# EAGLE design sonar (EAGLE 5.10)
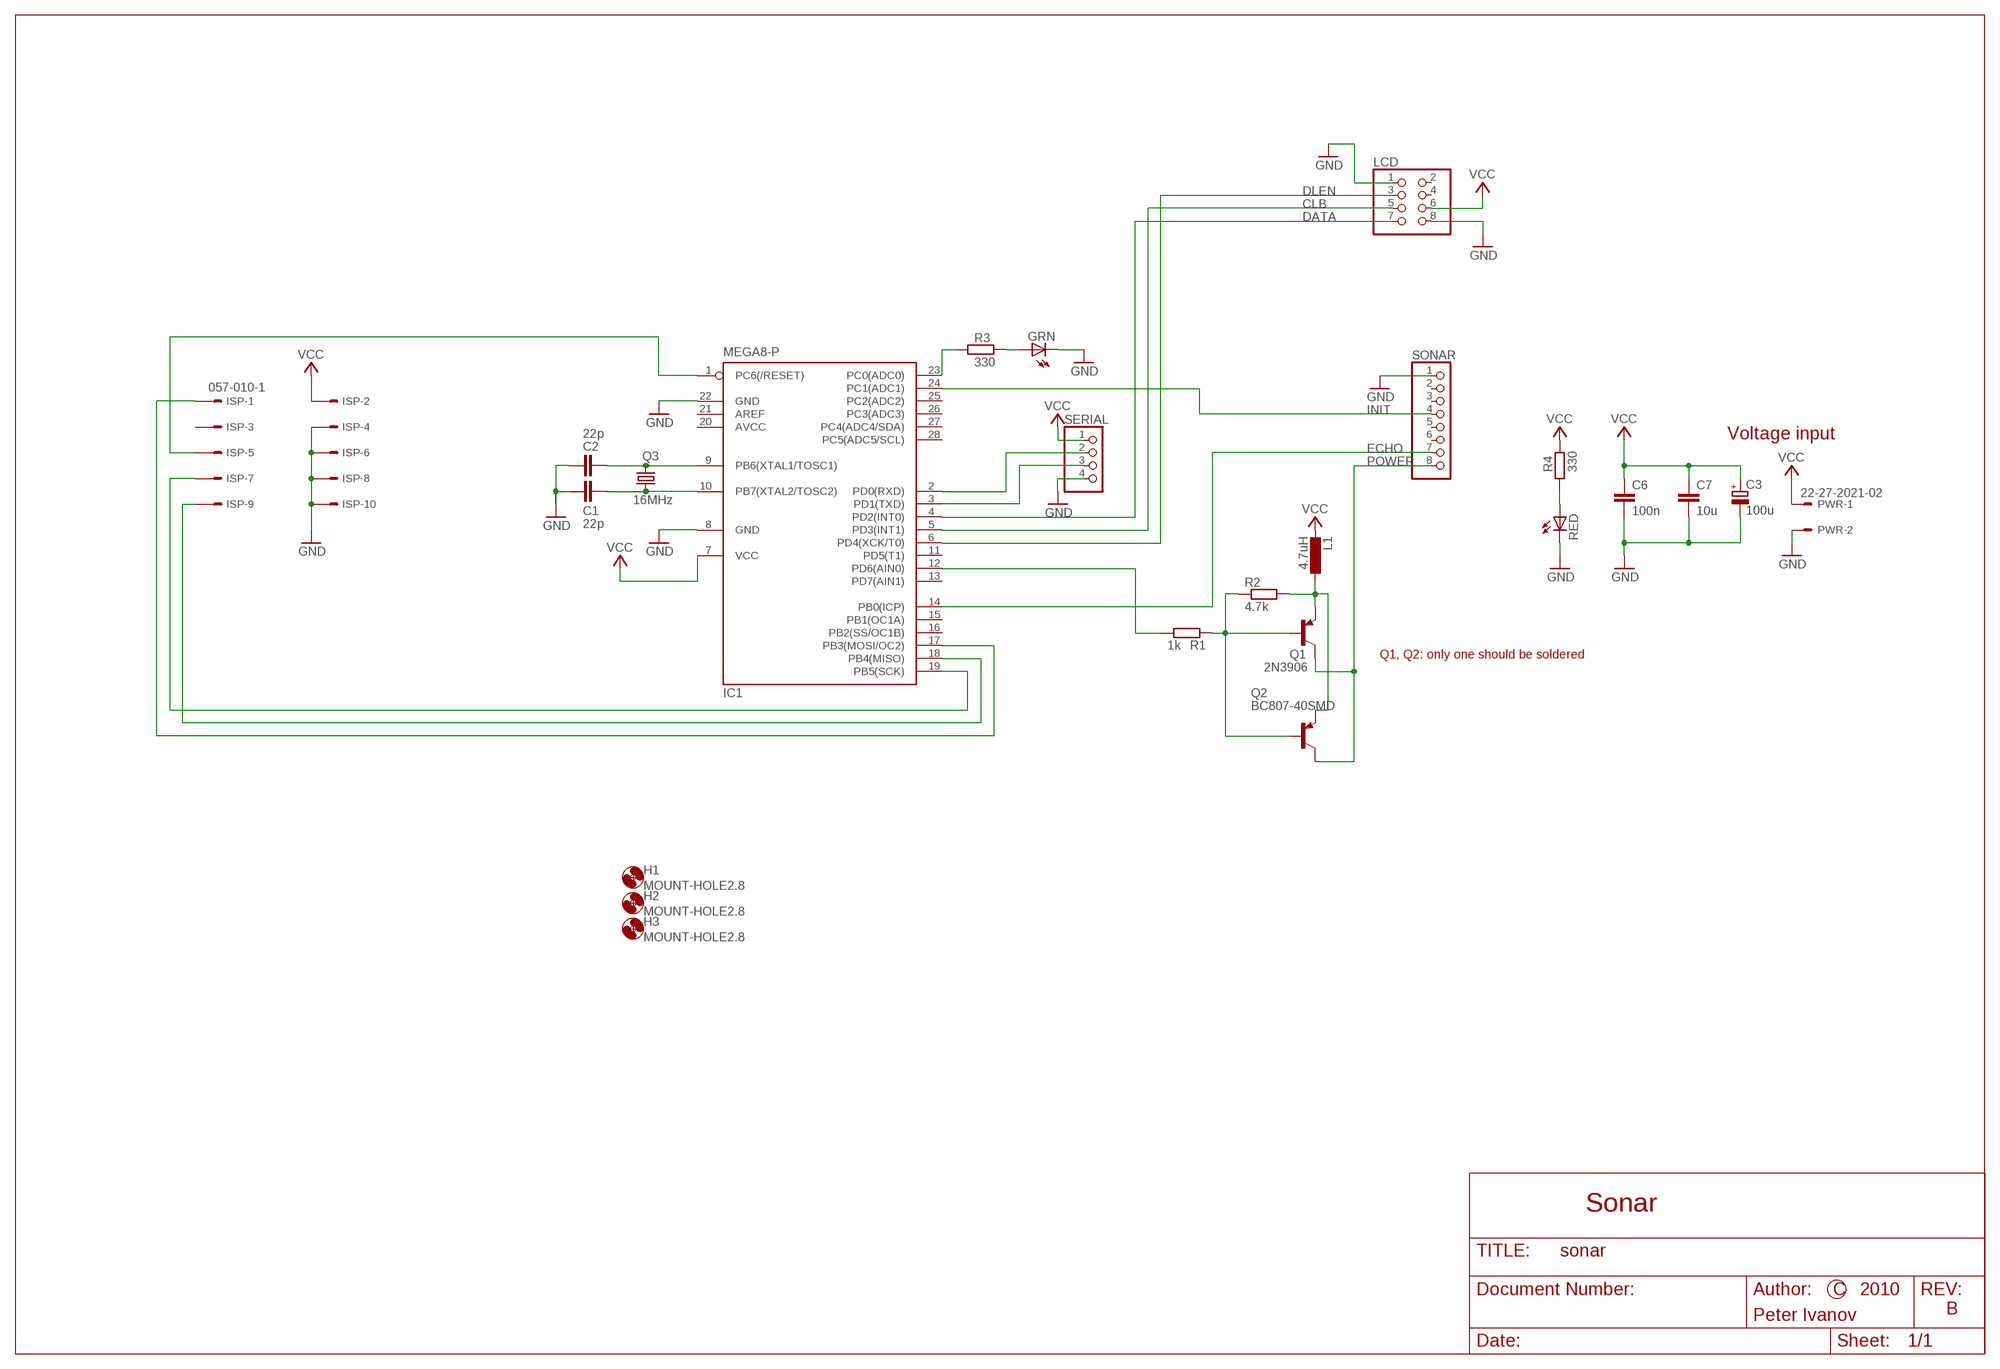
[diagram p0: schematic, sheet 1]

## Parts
C1  22p  C-EUC0805  [C0805]
C2  22p  C-EUC0805  [C0805]
C3  100u  CPOL-EUE2-5  [E2-5]
C6  100n  C-EUC0805  [C0805]
C7  10u  C-EUC1210  [C1210]
GRN  LED3MM  [LED3MM]
H1  MOUNT-HOLE2.8  [2,8]
H2  MOUNT-HOLE2.8  [2,8]
H3  MOUNT-HOLE2.8  [2,8]
IC1  MEGA8-P  [DIL28-3]
ISP  057-010-1  [057-010-1]
L1  4.7uH  L-EUL3230M  [L3230M]
LCD  PINHD-2X4  [2X04]
PWR  22-27-2021-02  [6410-02]
Q1  2N3906  [TO92]
Q2  BC807-40SMD  [SOT23-BEC]
Q3  16MHz  CRYSTALHC49S  [HC49/S]
R1  1k  R-EU_R0805  [R0805]
R2  4.7k  R-EU_R0805  [R0805]
R3  330  R-EU_R0805  [R0805]
R4  330  R-EU_R0805  [R0805]
RED  LED3MM  [LED3MM]
SERIAL  PINHD-1X4  [1X04]
SONAR  PINHD-1X8  [1X08]

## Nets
CLB: IC1.5(PD3(INT1)) LCD.5
DATA: IC1.4(PD2(INT0)) LCD.7
DLEN: IC1.6(PD4(XCK/T0)) LCD.3
ECHO: IC1.14(PB0(ICP)) SONAR.7
GND: C1.1 C2.1 C3.- C6.2 C7.2 GRN.K(C) IC1.8(GND) IC1.22(GND) ISP.4 ISP.6 ISP.8 ISP.10 LCD.1 LCD.8 PWR.2 RED.K(C) SERIAL.4 SONAR.1
INIT: IC1.24(PC1(ADC1)) SONAR.4
N$1: Q1.2(B) Q2.B R1.2 R2.1
N$2: L1.1 Q1.3(E) Q2.E R2.2
N$3: IC1.12(PD6(AIN0)) R1.1
N$4: IC1.17(PB3(MOSI/OC2)) ISP.1
N$5: IC1.19(PB5(SCK)) ISP.7
N$6: IC1.1(PC6(/RESET)) ISP.5
N$7: IC1.18(PB4(MISO)) ISP.9
N$8: C2.2 IC1.9(PB6(XTAL1/TOSC1)) Q3.2
N$9: C1.2 IC1.10(PB7(XTAL2/TOSC2)) Q3.1
N$10: R4.1 RED.A
N$11: IC1.23(PC0(ADC0)) R3.1
N$12: GRN.A R3.2
N$25: IC1.3(PD1(TXD)) SERIAL.3
N$26: IC1.2(PD0(RXD)) SERIAL.2
POWER: Q1.1(C) Q2.C SONAR.8
VCC: C3.+ C6.1 C7.1 IC1.7(VCC) ISP.2 L1.2 LCD.6 PWR.1 R4.2 SERIAL.1
Unconnected: IC1.11(PD5(T1)) IC1.13(PD7(AIN1)) IC1.15(PB1(OC1A)) IC1.16(PB2(SS/OC1B)) IC1.21(AREF) IC1.25(PC2(ADC2)) IC1.26(PC3(ADC3)) IC1.27(PC4(ADC4/SDA)) IC1.28(PC5(ADC5/SCL)) ISP.3 LCD.2 LCD.4 SONAR.2 SONAR.3 SONAR.5 SONAR.6

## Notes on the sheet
- Voltage input
- Q1, Q2: only one should be soldered
- Sonar
- Author: | C | 2010
- B
- Peter Ivanov

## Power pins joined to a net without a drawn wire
AVCC: IC1.20(AVCC)

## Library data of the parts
C1 C2 C6 C7 = rcl:C-EU: CAPACITOR, European symbol
C3 = rcl:CPOL-EU: POLARIZED CAPACITOR, European symbol
GRN RED = led:LED: LED
H1-H3 = holes:MOUNT-HOLE: MOUNTING HOLE with drill center marker
IC1 = atmel:MEGA8-P: MICROCONTROLLER 8 Kbytes FLASH, 1 kbytes SRAM, 512 bytes EEPROM, USART, 4-channel 10 bit ADC, 2-channel 8 bit ADC Pin compatible with Atmega48, ATMega88, ATMega168 Source: avr.lbr
ISP = con-panduit:057-010-: CONNECTOR 10-pin series 057 contact pc board low profile headers
L1 = rcl:L-EU: INDUCTOR, European symbol
LCD = pinhead:PINHD-2X4: PIN HEADER
PWR = con-molex:22-?-02: CONNECTOR
Q1 = transistor-pnp:2N3906: PNP Transistor
Q2 = transistor-pnp:BC807*: PNP Transistror
Q3 = crystal:CRYSTAL: CRYSTAL
R1-R4 = rcl:R-EU_: RESISTOR, European symbol
SERIAL = pinhead:PINHD-1X4: PIN HEADER
SONAR = pinhead:PINHD-1X8: PIN HEADER

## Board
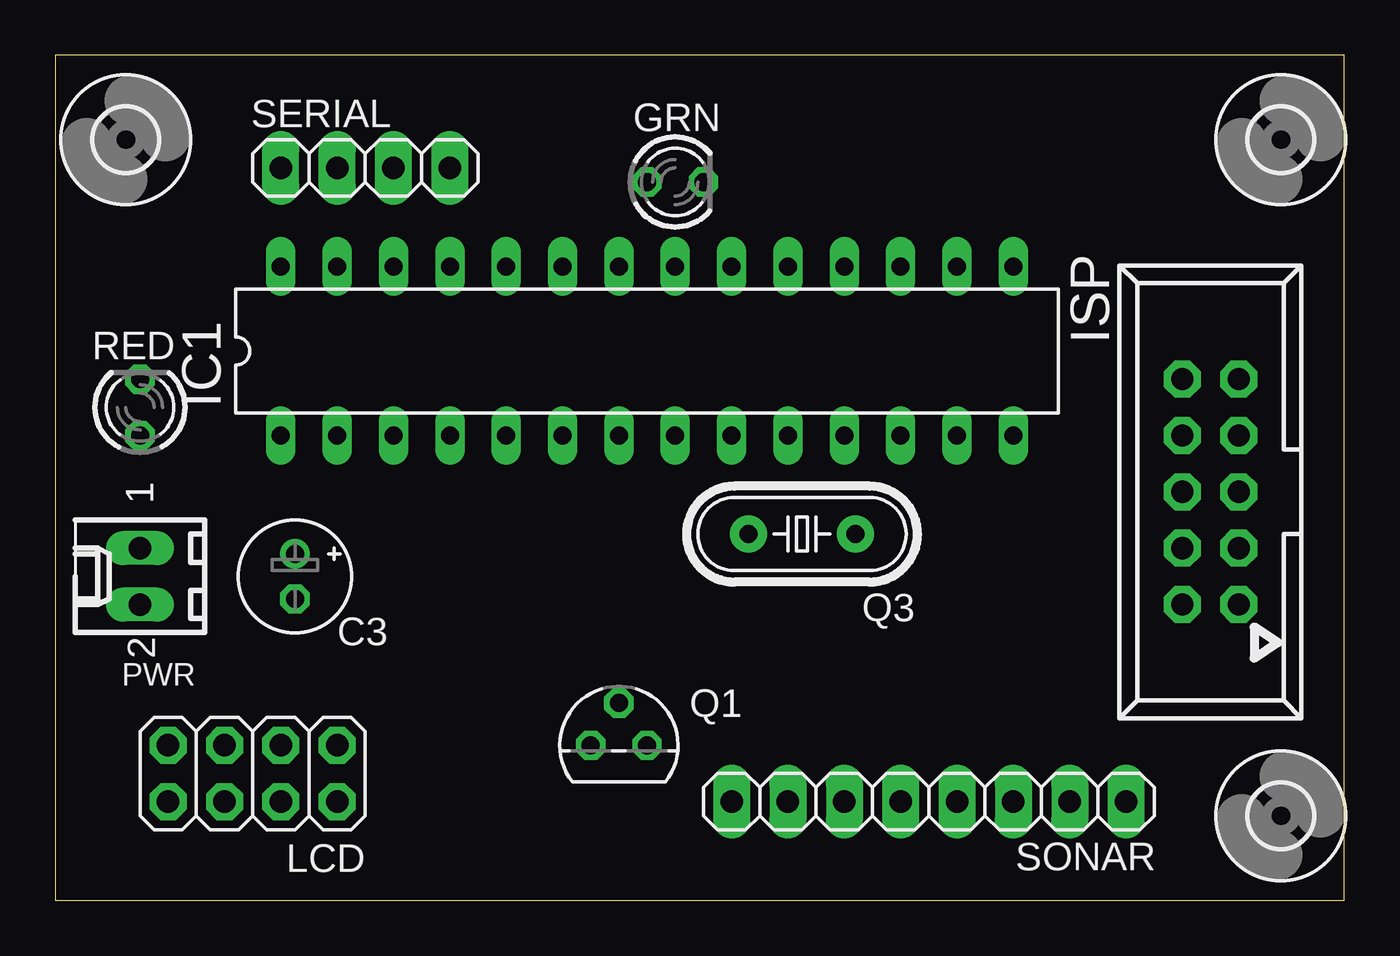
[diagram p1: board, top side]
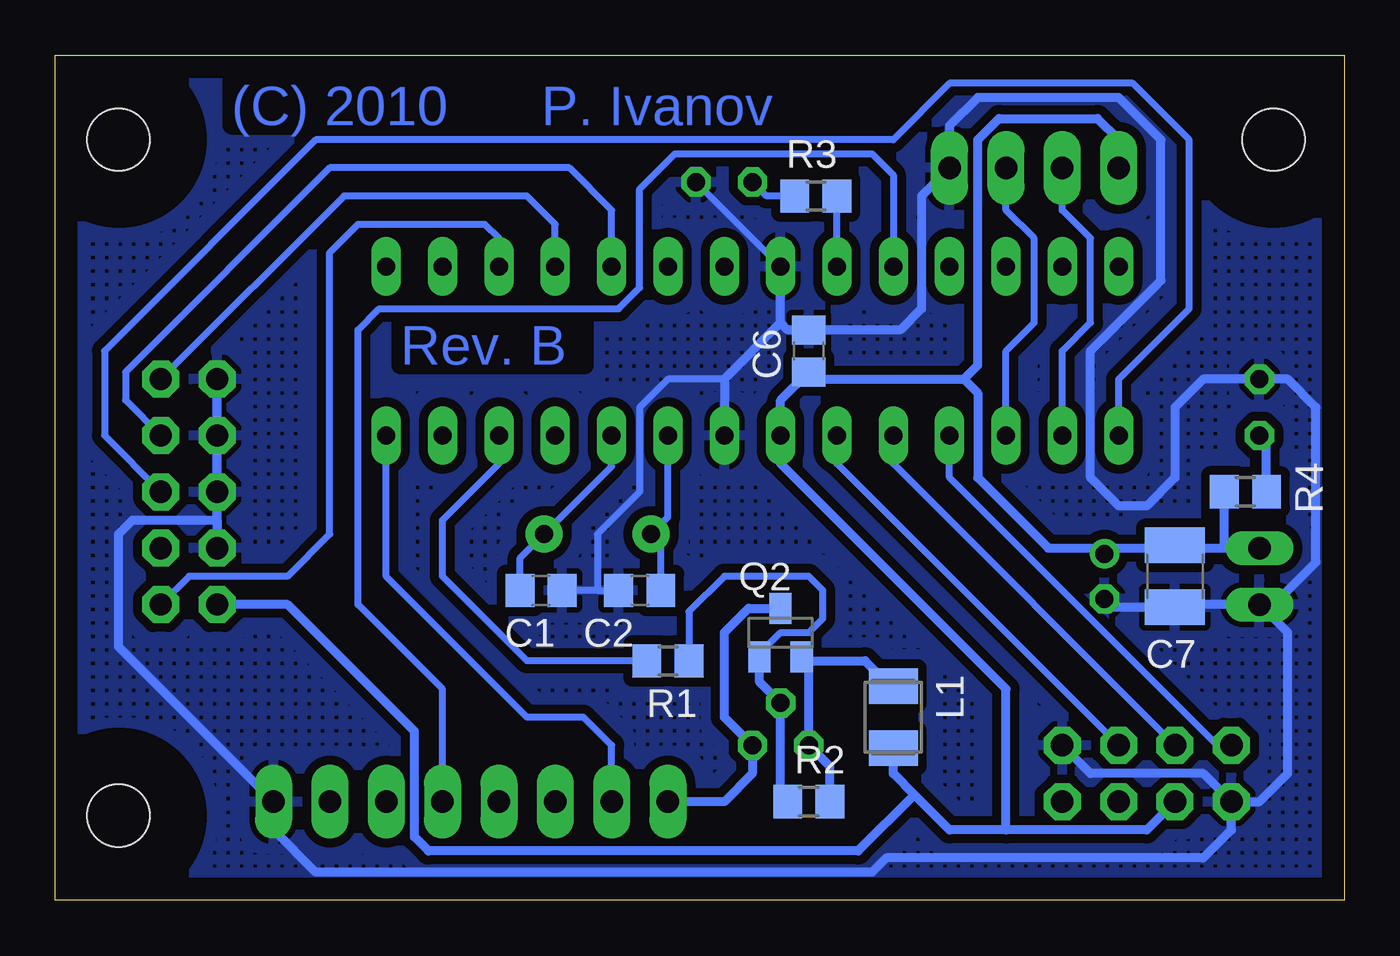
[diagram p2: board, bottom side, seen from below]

Size 58.09 x 38.09 mm. Coordinates in mm from the lower left corner, seen from the top.
Outline: 0,0 58.09,0 58.09,38.09 0,38.09 0,0
Copper layers (1*16): Top 0.035mm / dielectric 1.5mm / Bottom 0.035mm
Design rules "default": minimum track width 10mil, minimum drill 24mil, track to track 8mil, track to pad 8mil, pad to pad 8mil, via to via 8mil, smd to smd 8mil, copper to edge 40mil, drill to drill 8mil, minimum pad ring 10mil, minimum via ring 8mil, stop-mask expansion 4mil, vias tented up to drill 0mil, thermal gap 10mil

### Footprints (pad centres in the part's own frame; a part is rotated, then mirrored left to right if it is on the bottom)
C0805 = smd 1.3 x 1.5: 1 -0.95,0; 2 0.95,0
E2-5 = drill 0.813 pad 1.27 round: + -1.016,0 | drill 0.813 pad 1.27 octagon: - 1.016,0
C1210 = smd 1.6 x 2.7: 1 -1.4,0; 2 1.4,0
LED3MM = drill 0.813 octagon: A -1.27,0; K 1.27,0
2,8 = hole 2.8: 0,0
DIL28-3 = drill 0.813 long: 1 -16.51,-3.81; 2 -13.97,-3.81; 3 -11.43,-3.81; 4 -8.89,-3.81; 5 -6.35,-3.81; 6 -3.81,-3.81; 7 -1.27,-3.81; 8 1.27,-3.81; 9 3.81,-3.81; 10 6.35,-3.81; 11 8.89,-3.81; 12 11.43,-3.81; 13 13.97,-3.81; 14 16.51,-3.81; 15 16.51,3.81; 16 13.97,3.81; 17 11.43,3.81; 18 8.89,3.81; 19 6.35,3.81; 20 3.81,3.81; 21 1.27,3.81; 22 -1.27,3.81; 23 -3.81,3.81; 24 -6.35,3.81; 25 -8.89,3.81; 26 -11.43,3.81; 27 -13.97,3.81; 28 -16.51,3.81
057-010-1 = drill 1 pad 1.67 octagon: 1 -5.08,-1.27; 2 -5.08,1.27; 3 -2.54,-1.27; 4 -2.54,1.27; 5 0,-1.27; 6 0,1.27; 7 2.54,-1.27; 8 2.54,1.27; 9 5.08,-1.27; 10 5.08,1.27
L3230M = smd 1.6 x 2.2: 1 -1.4,0; 2 1.4,0
2X04 = drill 1.016 pad 1.67 octagon: 1 -3.81,-1.27; 2 -3.81,1.27; 3 -1.27,-1.27; 4 -1.27,1.27; 5 1.27,-1.27; 6 1.27,1.27; 7 3.81,-1.27; 8 3.81,1.27
6410-02 = drill 1.016 long: 1 1.27,0; 2 -1.27,0
TO92 = drill 0.813 octagon: 1 1.27,0; 2 0,1.905; 3 -1.27,0
SOT23-BEC = smd 1 x 1.4: B -0.95,-1.1; C 0,1.1; E 0.95,-1.1
HC49/S = drill 0.8 pad 1.67 round: 1 -2.413,0; 2 2.413,0
R0805 = smd 1.3 x 1.5: 1 -0.95,0; 2 0.95,0
1X04 = drill 1.016 pad 1.67 long: 1 -3.81,0; 2 -1.27,0; 3 1.27,0; 4 3.81,0
1X08 = drill 1.016 pad 1.67 long: 1 -8.89,0; 2 -6.35,0; 3 -3.81,0; 4 -1.27,0; 5 1.27,0; 6 3.81,0; 7 6.35,0; 8 8.89,0

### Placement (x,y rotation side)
C1  36.2,13.97 180 bottom
C2  31.75,13.97 0 bottom
C3  10.79,14.61 270 top
C6  24.13,24.77 90 bottom
C7  7.62,14.61 270 bottom
GRN  27.94,32.38 0 top
H1  55.24,3.81 0 top
H2  3.17,34.29 0 top
H3  55.24,34.29 0 top
IC1  26.67,24.77 0 top
ISP  52.07,18.41 90 top
L1  20.32,8.26 270 bottom
LCD  8.89,5.71 180 top
PWR  3.81,14.61 90 top
Q1  25.4,6.99 0 top
Q2  25.4,12.06 0 bottom
Q3  33.66,16.51 180 top
R1  30.48,10.79 0 bottom
R2  24.13,4.45 0 bottom
R3  23.81,31.75 180 bottom
R4  4.45,18.41 180 bottom
RED  3.81,22.23 90 top
SERIAL  13.97,33.02 0 top
SONAR  39.37,4.45 180 top

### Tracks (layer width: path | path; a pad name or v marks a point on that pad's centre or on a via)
CLB
  Bottom 0.305: IC1.5 20.32,19.68 LCD.5
DATA
  Bottom 0.305: IC1.4 17.78,19.05 5.71,6.99 LCD.7
DLEN
  Bottom 0.305: LCD.3 22.86,19.68 IC1.6
ECHO
  Bottom 0.305: SONAR.7 33.02,6.99 34.29,8.26 36.83,8.26 43.18,14.61 IC1.14
GND
  Bottom 0.305: 33.66,13.97 C2.1 | 33.66,13.97 C1.1 | 27.94,23.5 30.48,23.5 31.75,22.23 31.75,18.41 33.66,16.51 33.66,13.97 | IC1.22 GRN.K
  Bottom 0.406: IC1.8 27.94,23.5 25.4,26.04 | 25.4,26.04 IC1.22 | C6.2 25.08,25.71 25.4,26.04 | LCD.1 11.43,5.71 6.35,5.71 LCD.8 | LCD.8 3.81,4.45 2.54,5.71 2.54,12.06 PWR.2 | PWR.2 7.49,13.34 C7.2 10.41,13.21 C3.- | ISP.10 ISP.8 ISP.6 50.8,17.14 | 50.8,17.14 ISP.4 | 50.8,17.14 54.61,17.14 55.24,16.51 55.24,11.43 SONAR.1 48.26,3.17 46.35,1.27 21.27,1.27 20.64,1.91 6.35,1.91 5.08,3.17 LCD.8 | PWR.2 3.17,13.34 1.27,15.24 1.27,22.23 2.54,23.5 RED.K 6.35,23.5 7.62,22.23 7.62,19.05 8.89,17.78 10.16,17.78 11.43,19.05 11.43,24.77 8.26,27.94 8.26,34.29 10.16,36.2 16.51,36.2 17.78,34.92 SERIAL.4 19.05,31.75 19.05,26.67 20,25.71 C6.2 | C6.2 24.13,25.4
  pour Bottom (isolate 0.406, hatched): 0,38.1 0,0 58.42,0 58.42,38.1
INIT
  Bottom 0.305: SONAR.4 40.64,9.53 44.45,13.34 44.45,25.72 43.5,26.67 32.7,26.67 31.75,27.62 31.75,32.07 30.16,33.66 21.27,33.66 20.32,32.7 IC1.24
N$1
  Bottom 0.305: R2.1 25.4,4.76 | 26.35,11.12 25.4,12.06 24.13,12.06 23.5,12.7 23.5,13.97 24.13,14.61 27.94,14.61 29.53,13.02 R1.2
  Bottom 0.406: 25.4,4.76 Q1.2 26.35,9.84 Q2.B 26.35,11.12
N$2
  Bottom 0.305: 24.13,10.64 Q2.E 24.15,10.66
  Bottom 0.406: 24.13,10.64 Q1.3 23.18,6.04 R2.2 | L1.1 20.45,9.65 21.59,10.79 24.28,10.79 Q2.E
N$3
  Bottom 0.305: R1.1 36.83,10.79 40.64,14.61 40.64,17.14 38.1,19.68 IC1.12
N$4
  Bottom 0.305: IC1.17 38.1,29.84 38.73,30.48 44.45,30.48 45.72,29.21 45.72,16.51 47.62,14.61 52.07,14.61 ISP.1
N$5
  Bottom 0.305: IC1.19 33.02,31.11 34.92,33.02 45.72,33.02 54.93,23.81 54.93,22.54 ISP.7
N$6
  Bottom 0.305: IC1.1 10.16,23.5 6.99,26.67 6.99,34.29 9.53,36.83 17.78,36.83 20.32,34.29 46.35,34.29 55.88,24.77 55.88,20.95 ISP.5
N$7
  Bottom 0.305: IC1.18 35.56,30.48 36.83,31.75 45.09,31.75 ISP.9
N$8
  Bottom 0.305: IC1.9 30.48,17.27 Q3.2 30.8,16.07 C2.2
N$9
  Bottom 0.305: IC1.10 33.02,19.56 Q3.1 37.15,15.43 C1.2
N$10
  Bottom 0.406: R4.1 3.5,20.64 RED.A
N$11
  Bottom 0.305: IC1.23 R3.1
N$12
  Bottom 0.305: R3.2 26.04,31.75 GRN.A
N$25
  Bottom 0.305: IC1.3 15.24,24.77 13.97,26.04 13.97,29.84 15.24,31.11 SERIAL.3
N$26
  Bottom 0.305: IC1.2 12.7,24.77 11.43,26.04 11.43,29.84 12.7,31.11 SERIAL.2
POWER
  Bottom 0.406: Q2.C 26.84,13.16 27.94,12.06 27.94,8.26 Q1.1 26.67,5.71 27.94,4.45 SONAR.8
VCC
  Bottom 0.406: LCD.6 8.89,3.17 15.24,3.17 | 15.24,3.17 17.78,3.17 19.37,4.76 | 19.37,4.76 20.32,5.71 L1.2 | 7.49,15.88 5.39,15.88 | 7.49,15.88 C7.1 | 10.79,15.88 13.34,15.88 16.51,19.05 16.51,22.86 17.14,23.5 | 10.79,15.88 7.49,15.88 | 17.14,23.5 23.81,23.5 C6.1 25.4,22.55 IC1.7 25.4,19.68 15.24,9.53 15.24,3.17 | ISP.2 47.62,13.34 41.91,7.62 41.91,2.86 41.27,2.22 21.91,2.22 19.37,4.76 | 5.39,15.88 R4.2 | 5.39,15.88 PWR.1 | 10.79,15.88 C3.+ | 17.14,23.5 16.51,24.13 16.51,34.29 15.56,35.24 11.11,35.24 10.16,34.29 SERIAL.1

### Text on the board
Bottom: P. Ivanov | (C) 2010 | Rev. B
